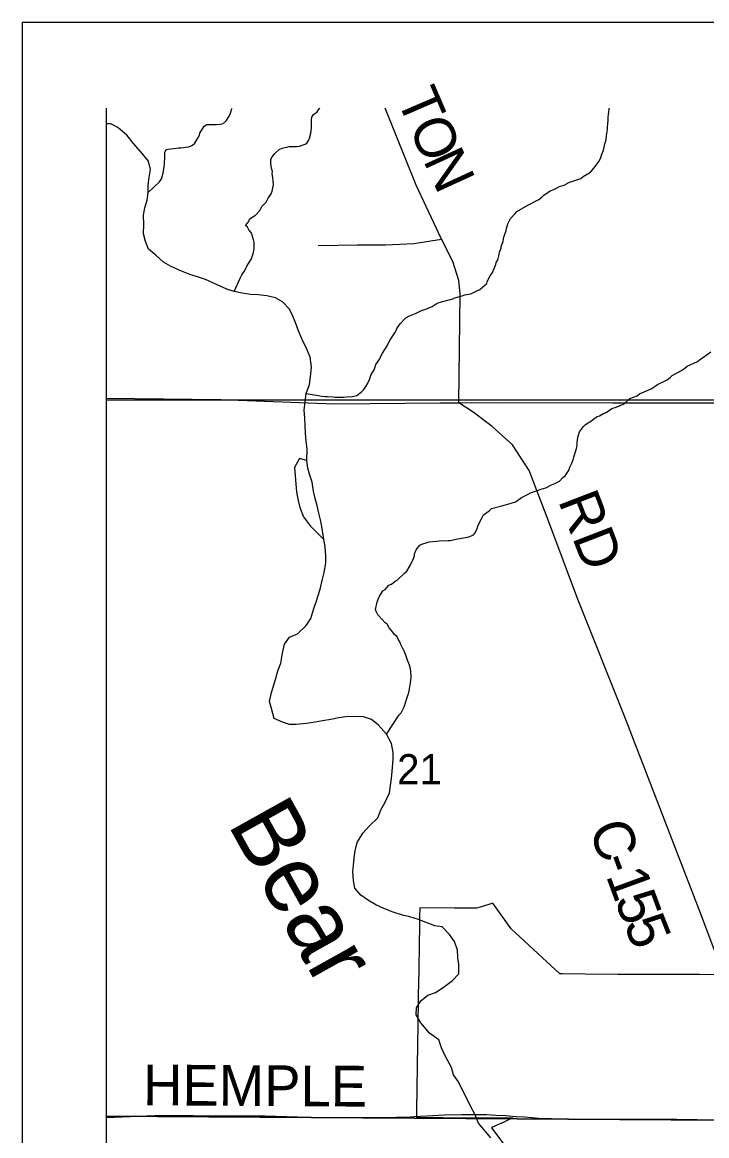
# Model space of a CAD drawing. Extents: x 0 to 34, y 0 to 22.
# Drawn here: x 2 to 2.955, y 15.768 to 17.321 of the extents above; entities that cross this region are included whole.
import ezdxf

# ---------------------------------------------------------------- set-up
doc = ezdxf.new("R2010")
doc.units = 0
for name, color, linetype in [('GM_X_County_Road', 7, 'Continuous'), ('GM_X_County_Road_Text', 7, 'Continuous'), ('GM_X_Interchange_Ramps', 7, 'Continuous'), ('GM_X_Interstate_Route', 7, 'Continuous'), ('GM_X_Minor_River', 7, 'Continuous'), ('GM_X_Minor_River_Text', 7, 'Continuous'), ('GM_X_Section_Text', 7, 'Continuous'), ('GM_X_State_Shield', 7, 'Continuous'), ('GM_X_Township_Road', 7, 'Continuous'), ('GM_X_Township_Road_Text', 7, 'Continuous'), ('SH_Data', 7, 'Continuous')]:
    doc.layers.add(name, color=color, linetype=linetype)

msp = doc.modelspace()

# ---------------------------------------------------------------- linework, layer by layer
at = {"layer": 'GM_X_County_Road'}
for points in [[(2.9739, 16.0048), (2.9448, 16.0825), (2.8399, 16.3533), (2.7746, 16.5176), (2.7346, 16.6245), (2.707, 16.6961), (2.6839, 16.7319), (2.6556, 16.7576), (2.6288, 16.7772), (2.6089, 16.7905), (2.6107, 16.9419), (2.6089, 16.9612), (2.6005, 16.9874), (2.5848, 17.0188), (2.5494, 17.0939), (2.5063, 17.2013)], [(2.1171, 16.7968), (2.2769, 16.7951), (2.4356, 16.7891), (2.5828, 16.7904), (2.6089, 16.7905), (2.664, 16.7909), (2.8237, 16.7904), (3.0081, 16.7905), (3.0639, 16.7903), (3.1192, 16.79), (3.3661, 16.7938), (3.6388, 16.7936), (4.0443, 16.793), (4.283, 16.7943)]]:
    msp.add_lwpolyline(points, dxfattribs=at)
at = {"layer": 'GM_X_Interchange_Ramps'}
msp.add_lwpolyline([(2.975, 15.9929), (2.9447, 15.993), (2.8987, 15.9931), (2.8721, 15.9931), (2.844, 15.9932), (2.8308, 15.9932), (2.7852, 15.9937), (2.7537, 15.994), (2.7497, 15.994), (2.6821, 16.0567), (2.6585, 16.0893), (2.6563, 16.0925), (2.6418, 16.088), (2.6337, 16.0856), (2.631, 16.0856), (2.6026, 16.0859), (2.5543, 16.0863), (2.5541, 16.0736), (2.5541, 16.071), (2.5539, 16.0558), (2.5536, 16.0397), (2.5529, 15.9959), (2.5528, 15.9845), (2.5524, 15.9614), (2.5518, 15.9217), (2.5514, 15.896), (2.55, 15.8037), (2.55, 15.8037), (2.5499, 15.8022), (2.5499, 15.7999), (2.5499, 15.7988), (2.55, 15.7942), (2.5698, 15.794), (2.5865, 15.7939), (2.6838, 15.7931), (2.6678, 15.7856), (2.667, 15.7853), (2.6593, 15.7817), (2.656, 15.7802), (2.6545, 15.7795), (2.6549, 15.779), (2.6805, 15.7443)], dxfattribs=at)
at = {"layer": 'GM_X_Interstate_Route'}
msp.add_line((2.1171, 17.2013), (2.1171, 14.0019), dxfattribs=at)
at = {"layer": 'GM_X_Minor_River'}
for points in [[(2.1755, 17.0835), (2.1913, 17.0984), (2.1941, 17.1029), (2.1953, 17.1059), (2.1966, 17.1105), (2.198, 17.12), (2.1984, 17.1226), (2.1985, 17.1253), (2.199, 17.131), (2.1988, 17.1363), (2.1989, 17.1401), (2.2009, 17.1431), (2.2036, 17.1442), (2.2074, 17.1445), (2.212, 17.1451), (2.2181, 17.1458), (2.2212, 17.1461), (2.2319, 17.1473), (2.2346, 17.1484), (2.2373, 17.1499), (2.2408, 17.1524), (2.2455, 17.1603), (2.2471, 17.1637), (2.2476, 17.1664), (2.2516, 17.1727), (2.2539, 17.1761), (2.2574, 17.1783), (2.2609, 17.1786), (2.2639, 17.1785), (2.2704, 17.1787), (2.2754, 17.179), (2.2788, 17.1793), (2.2823, 17.1811), (2.2847, 17.1841), (2.2878, 17.1886), (2.2898, 17.1931), (2.2915, 17.1969), (2.2919, 17.1995), (2.2928, 17.2013)], [(2.2954, 16.9455), (2.3045, 16.965), (2.3062, 16.9691), (2.3101, 16.974), (2.3133, 16.9811), (2.3157, 16.9845), (2.3197, 16.9913), (2.321, 16.9958), (2.3226, 17), (2.323, 17.0026), (2.3235, 17.0057), (2.3233, 17.014), (2.3227, 17.0179), (2.3206, 17.0244), (2.3191, 17.0279), (2.3158, 17.0318), (2.314, 17.0352), (2.3114, 17.0376), (2.3161, 17.0432), (2.3169, 17.0466), (2.3208, 17.0491), (2.3251, 17.0521), (2.3313, 17.0584), (2.3329, 17.0614), (2.3342, 17.0641), (2.34, 17.0704), (2.3428, 17.0757), (2.3452, 17.079), (2.3472, 17.082), (2.3484, 17.0854), (2.3497, 17.0903), (2.3502, 17.0945), (2.35, 17.1006), (2.3497, 17.1041), (2.3487, 17.1102), (2.3488, 17.1132), (2.3477, 17.1178), (2.3468, 17.1243), (2.3469, 17.13), (2.3485, 17.1334), (2.3525, 17.1379), (2.3583, 17.1438), (2.3626, 17.1453), (2.3725, 17.1477), (2.3764, 17.148), (2.3825, 17.1478), (2.3867, 17.1485), (2.3905, 17.1495), (2.3944, 17.1513), (2.3971, 17.1524), (2.399, 17.1554), (2.4007, 17.1596), (2.4024, 17.1664), (2.4033, 17.1736), (2.4035, 17.182), (2.4032, 17.185), (2.4041, 17.1888), (2.4061, 17.1926), (2.4111, 17.1962), (2.4143, 17.2004), (2.4152, 17.2013)], [(2.3962, 16.8034), (2.4127, 16.8004), (2.4173, 16.7999), (2.4226, 16.7994), (2.4257, 16.7994), (2.4333, 16.7988), (2.4363, 16.7983), (2.4481, 16.7984), (2.4516, 16.7987), (2.46, 16.7993), (2.4627, 16.7996), (2.4665, 16.8006), (2.4735, 16.8062), (2.4763, 16.8092), (2.4794, 16.8133), (2.4814, 16.817), (2.4842, 16.8227), (2.4855, 16.8265), (2.4863, 16.8291), (2.4907, 16.8362), (2.4923, 16.8408), (2.4932, 16.8438), (2.4987, 16.8517), (2.5007, 16.8566), (2.5023, 16.8596), (2.5091, 16.8697), (2.5115, 16.875), (2.5131, 16.8784), (2.5198, 16.8881), (2.5219, 16.8922), (2.5231, 16.8949), (2.5274, 16.9012), (2.5325, 16.9068), (2.5352, 16.9087), (2.5391, 16.9112), (2.5487, 16.9148), (2.5569, 16.9192), (2.5615, 16.9206), (2.5715, 16.9249), (2.5789, 16.9293), (2.5846, 16.9311), (2.5954, 16.9339), (2.6004, 16.9353), (2.6034, 16.9367), (2.6134, 16.9395), (2.6173, 16.9409), (2.6257, 16.9426), (2.633, 16.9463), (2.6381, 16.9484), (2.6478, 16.9566), (2.6486, 16.9596), (2.6527, 16.9675), (2.6558, 16.972), (2.6566, 16.9746), (2.6607, 16.9833), (2.6611, 16.986), (2.6631, 16.9897), (2.6648, 16.9954), (2.6661, 17.0018), (2.6678, 17.006), (2.6682, 17.0086), (2.6707, 17.0154), (2.6711, 17.0189), (2.6716, 17.0215), (2.674, 17.0279), (2.6749, 17.0309), (2.6753, 17.0336), (2.6774, 17.04), (2.681, 17.0476), (2.6873, 17.0546), (2.6897, 17.0572), (2.7017, 17.0642), (2.7059, 17.0664), (2.7206, 17.074), (2.7249, 17.0773), (2.7276, 17.0799), (2.7361, 17.0858), (2.7415, 17.088), (2.7504, 17.0927), (2.7558, 17.0941), (2.7635, 17.0981), (2.7681, 17.0995), (2.7789, 17.1034), (2.7824, 17.106), (2.7925, 17.1122), (2.7952, 17.1152), (2.8004, 17.122), (2.8047, 17.1272), (2.8071, 17.1325), (2.808, 17.1359), (2.8108, 17.1426), (2.8126, 17.1514), (2.8138, 17.1551), (2.8152, 17.1658), (2.8161, 17.1715), (2.8162, 17.1749), (2.8172, 17.1844), (2.8173, 17.1893), (2.8178, 17.192), (2.8184, 17.2), (2.8184, 17.2013)], [(2.3933, 16.7803), (2.3962, 16.8034), (2.4008, 16.8159), (2.4022, 16.8268), (2.4033, 16.8401), (2.4014, 16.8539), (2.3968, 16.8654), (2.3903, 16.8789), (2.3853, 16.8908), (2.3814, 16.9008), (2.3775, 16.9112), (2.3728, 16.9209), (2.3632, 16.9314), (2.3531, 16.937), (2.3409, 16.9396), (2.3292, 16.9411), (2.3185, 16.9414), (2.3068, 16.9433), (2.2954, 16.9455), (2.2852, 16.9488), (2.2717, 16.9549), (2.2555, 16.9622), (2.2446, 16.9659), (2.2337, 16.9693), (2.2197, 16.975), (2.2066, 16.9811), (2.1968, 16.9867), (2.1864, 16.9961), (2.176, 17.0048), (2.1717, 17.0155), (2.169, 17.0259), (2.1697, 17.0392), (2.1693, 17.0521), (2.1711, 17.0623), (2.1744, 17.0729), (2.1755, 17.0835), (2.1754, 17.0945), (2.1772, 17.1044), (2.1787, 17.1157), (2.1759, 17.1276), (2.1656, 17.1404), (2.1553, 17.1518), (2.1461, 17.1631), (2.1334, 17.1744), (2.1237, 17.1793), (2.1171, 17.1795)], [(2.802, 16.7711), (2.805, 16.7722), (2.8105, 16.7755), (2.8143, 16.7769), (2.8225, 16.7824), (2.8282, 16.7842), (2.8394, 16.7892), (2.8476, 16.7963), (2.8576, 16.8002), (2.8611, 16.8028), (2.8773, 16.81), (2.8827, 16.8137), (2.8859, 16.8159), (2.8994, 16.8224), (2.9036, 16.8257), (2.9064, 16.8284), (2.9195, 16.8353), (2.9246, 16.839), (2.9273, 16.8416), (2.9416, 16.8481), (2.9466, 16.8517), (2.9501, 16.8543), (2.9606, 16.8613)], [(2.5173, 16.0799), (2.5042, 16.0852), (2.4933, 16.0904), (2.4831, 16.0964), (2.4723, 16.1036), (2.4638, 16.1137), (2.4618, 16.1241), (2.461, 16.1363), (2.462, 16.1457), (2.4631, 16.156), (2.4641, 16.1658), (2.4671, 16.1772), (2.475, 16.1903), (2.4841, 16.2007), (2.4958, 16.2117), (2.4999, 16.2227), (2.5059, 16.2328), (2.5124, 16.2467), (2.5139, 16.2599), (2.5153, 16.2709), (2.5164, 16.2823), (2.5171, 16.2929), (2.5173, 16.3028), (2.515, 16.3154), (2.5081, 16.3282), (2.4967, 16.3407), (2.487, 16.349), (2.4761, 16.3527), (2.4631, 16.3531), (2.4509, 16.3526), (2.4414, 16.351), (2.4306, 16.3486), (2.4188, 16.3471), (2.4085, 16.3451), (2.3966, 16.3431), (2.3821, 16.342), (2.3726, 16.3419), (2.3628, 16.3449), (2.3515, 16.3501), (2.3477, 16.3639), (2.3449, 16.3739), (2.3476, 16.3864), (2.353, 16.4045), (2.3564, 16.4166), (2.3605, 16.4275), (2.3628, 16.4411), (2.3658, 16.454), (2.3729, 16.4636), (2.384, 16.4683), (2.3962, 16.4797), (2.4025, 16.4898), (2.4067, 16.5034), (2.4104, 16.5143), (2.4154, 16.5305), (2.4184, 16.5426), (2.421, 16.5536), (2.4233, 16.5668), (2.4235, 16.5767), (2.4224, 16.5901), (2.4204, 16.6), (2.4188, 16.6122), (2.4165, 16.6252), (2.4138, 16.6367), (2.4114, 16.6471), (2.4086, 16.657), (2.4062, 16.6674), (2.4043, 16.6796), (2.4011, 16.6896), (2.3983, 16.6995), (2.3971, 16.7098), (2.3975, 16.7254), (2.396, 16.7376), (2.3951, 16.7475), (2.3947, 16.7594), (2.3942, 16.7693), (2.3933, 16.7803)], [(2.5081, 16.3282), (2.5255, 16.3553), (2.5283, 16.3579), (2.5327, 16.3666), (2.5339, 16.3707), (2.5348, 16.3738), (2.5384, 16.3836), (2.5397, 16.3885), (2.5402, 16.3919), (2.5415, 16.3995), (2.5425, 16.4075), (2.542, 16.4163), (2.5413, 16.4193), (2.5403, 16.4247), (2.5374, 16.4316), (2.5353, 16.437), (2.5331, 16.4432), (2.5302, 16.4489), (2.5281, 16.4536), (2.5266, 16.457), (2.5244, 16.4609), (2.523, 16.464), (2.5193, 16.4675), (2.5152, 16.4729), (2.5119, 16.4768), (2.509, 16.4818), (2.506, 16.4838), (2.5019, 16.4881), (2.496, 16.4947), (2.4934, 16.4994), (2.4927, 16.5021), (2.4949, 16.5123), (2.4969, 16.5176), (2.4985, 16.521), (2.5029, 16.5281), (2.506, 16.5303), (2.5115, 16.5363), (2.515, 16.5377), (2.52, 16.5418), (2.5231, 16.5432), (2.5337, 16.5533), (2.5364, 16.5555), (2.5396, 16.5611), (2.5412, 16.5637), (2.5456, 16.5732), (2.5469, 16.5773), (2.5473, 16.58), (2.5494, 16.5853), (2.5545, 16.592), (2.5572, 16.5934), (2.5676, 16.5966), (2.5779, 16.5975), (2.5817, 16.5978), (2.5939, 16.5983), (2.597, 16.5986), (2.6077, 16.6006), (2.6104, 16.6013), (2.6181, 16.6026), (2.6211, 16.6029), (2.6242, 16.604), (2.6296, 16.6062), (2.6316, 16.6092), (2.6344, 16.6152), (2.6353, 16.6186), (2.6401, 16.628), (2.6417, 16.6314), (2.6433, 16.634), (2.6514, 16.6399), (2.6546, 16.6429), (2.6691, 16.6467), (2.6741, 16.6481), (2.6772, 16.6492), (2.688, 16.6524), (2.6907, 16.6542), (2.6961, 16.6582), (2.7058, 16.663), (2.7089, 16.6648), (2.7185, 16.668), (2.7235, 16.6702), (2.7304, 16.6719), (2.7381, 16.6759), (2.7428, 16.6777), (2.7493, 16.6813), (2.754, 16.6862), (2.7571, 16.6884), (2.7627, 16.697), (2.7635, 16.6996), (2.7664, 16.7064), (2.7684, 16.711), (2.7693, 16.7147), (2.773, 16.7265), (2.7739, 16.7318), (2.774, 16.7348), (2.7749, 16.7424), (2.7758, 16.7451), (2.777, 16.75), (2.7829, 16.7575), (2.7857, 16.7601), (2.7942, 16.7656), (2.7973, 16.7682), (2.802, 16.7711)], [(2.3971, 16.7098), (2.3866, 16.7126), (2.3795, 16.7002), (2.3826, 16.6659), (2.3846, 16.6541), (2.3871, 16.6445), (2.3921, 16.6315), (2.4018, 16.6184), (2.4204, 16.6)], [(2.6534, 15.7656), (2.6364, 15.7858), (2.6311, 15.7982), (2.6253, 15.8097), (2.6199, 15.8202), (2.6141, 15.8321), (2.6083, 15.8433), (2.6017, 15.8534), (2.5986, 15.8634), (2.5895, 15.8807), (2.5849, 15.8908), (2.581, 15.9019), (2.5679, 15.9114), (2.5561, 15.9258), (2.5492, 15.9371), (2.5498, 15.9465), (2.5558, 15.9567), (2.5656, 15.9644), (2.5763, 15.9683), (2.5872, 15.9752), (2.6, 15.9847), (2.609, 15.9943), (2.609, 16.0073), (2.6077, 16.0168), (2.6072, 16.0271), (2.603, 16.039), (2.5957, 16.0491), (2.5857, 16.0597), (2.5754, 16.0611), (2.5634, 16.0656), (2.5528, 16.0701), (2.5408, 16.0735), (2.5305, 16.0757), (2.5173, 16.0799)]]:
    msp.add_lwpolyline(points, dxfattribs=at)
at = {"layer": 'GM_X_State_Shield'}
msp.add_lwpolyline([(2.1171, 17.2013), (2.1171, 16.794), (3.0664, 16.7946), (3.0714, 17.2013)], dxfattribs=at)
for points in [[(2.1171, 16.794), (2.1171, 15.7957), (3.0481, 15.7894), (3.0664, 16.7946)], [(2.1171, 15.7957), (2.1171, 14.8034), (3.0289, 14.7963), (3.0481, 15.7894)]]:
    msp.add_lwpolyline(points, close=True, dxfattribs=at)
at = {"layer": 'GM_X_Township_Road'}
for points in [[(2.4128, 17.01), (2.4671, 17.0107), (2.5065, 17.0107), (2.5462, 17.0126), (2.5848, 17.0188)], [(2.1171, 15.7938), (2.1955, 15.797), (2.2818, 15.796), (2.3386, 15.7959), (2.3989, 15.7941), (2.467, 15.7938)], [(2.467, 15.7938), (2.469, 15.7938), (2.5016, 15.7937), (2.5416, 15.7948), (2.5465, 15.7951)], [(2.5465, 15.7951), (2.5643, 15.796), (2.5889, 15.7974), (2.613, 15.7981), (2.6289, 15.798), (2.6475, 15.7981), (2.6607, 15.7972), (2.6741, 15.7966), (2.689, 15.7953), (2.7011, 15.7945), (2.7205, 15.793), (2.7383, 15.7923), (2.7608, 15.7916), (2.7958, 15.7916), (2.8456, 15.7914), (2.9128, 15.7914), (3.0543, 15.7893), (3.5501, 15.7858)]]:
    msp.add_lwpolyline(points, dxfattribs=at)
at = {"layer": 'SH_Data'}
for q in [(9, 17.3211), (2, 14)]:
    msp.add_line((2, 17.3211), q, dxfattribs=at)

# ---------------------------------------------------------------- texts
at = {"layer": 'GM_X_County_Road_Text'}
for s, height, rotation, p in [('T', 0.0568, 293.2476, (2.5216, 17.2151)), ('O', 0.0568, 293.3161, (2.5384, 17.176)), ('N', 0.0568, 294.6512, (2.5587, 17.1288)), ('RD', 0.05682, 291.0748, (2.7469, 16.6542)), ('C', 0.0568, 289.9631, (2.7897, 16.1971)), ('-', 0.0568, 289.9767, (2.8057, 16.1532)), ('1', 0.0568, 290.0801, (2.8137, 16.1312)), ('5', 0.0568, 290.3809, (2.8258, 16.098)), ('5', 0.0568, 291.6867, (2.8385, 16.0639))]:
    msp.add_text(s, height=height, rotation=rotation, dxfattribs=at).set_placement(p)
at = {"layer": 'GM_X_Minor_River_Text'}
msp.add_text('Bear', height=0.09476, rotation=299.1653, dxfattribs=at).set_placement((2.2856, 16.2034))
at = {"layer": 'GM_X_Section_Text'}
msp.add_text('21', height=0.04186, rotation=0, dxfattribs=at).set_placement((2.5229, 16.2586))
at = {"layer": 'GM_X_Township_Road_Text'}
msp.add_text('HEMPLE', height=0.05682, rotation=359.6583, dxfattribs=at).set_placement((2.1684, 15.8108))

doc.saveas('drawing.dxf')
